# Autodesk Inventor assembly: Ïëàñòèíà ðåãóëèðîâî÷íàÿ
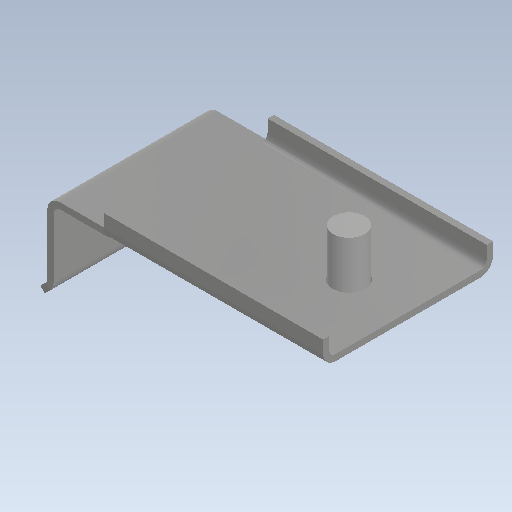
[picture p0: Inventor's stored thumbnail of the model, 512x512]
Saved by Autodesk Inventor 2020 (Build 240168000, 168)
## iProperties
Created: 1900-01
Part Number: Ïëàñòèíà ðåãóëèðîâî÷íàÿ
Document SubType Name: Assembly
Designer: bruno
Author: bruno
Revision Number: ANYUNSPECIFIED
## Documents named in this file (3)
- C:\Users\bruno\Documents\1-Cours-2022-23\1SI\2. Cinématique\Hoverboard\Inventor-Hoverboard\Platine-male.iam
- C:\Users\bruno\Documents\1-Cours-2022-23\1SI\2. Cinématique\Hoverboard\Inventor-Hoverboard\Platine-femelle.ipt
- C:\Users\bruno\Documents\1-Cours-2022-23\1SI\2. Cinématique\Hoverboard\Inventor-Hoverboard\Cylondre.ipt
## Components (2 placed, 2 different names)
1. 17
2. 18
